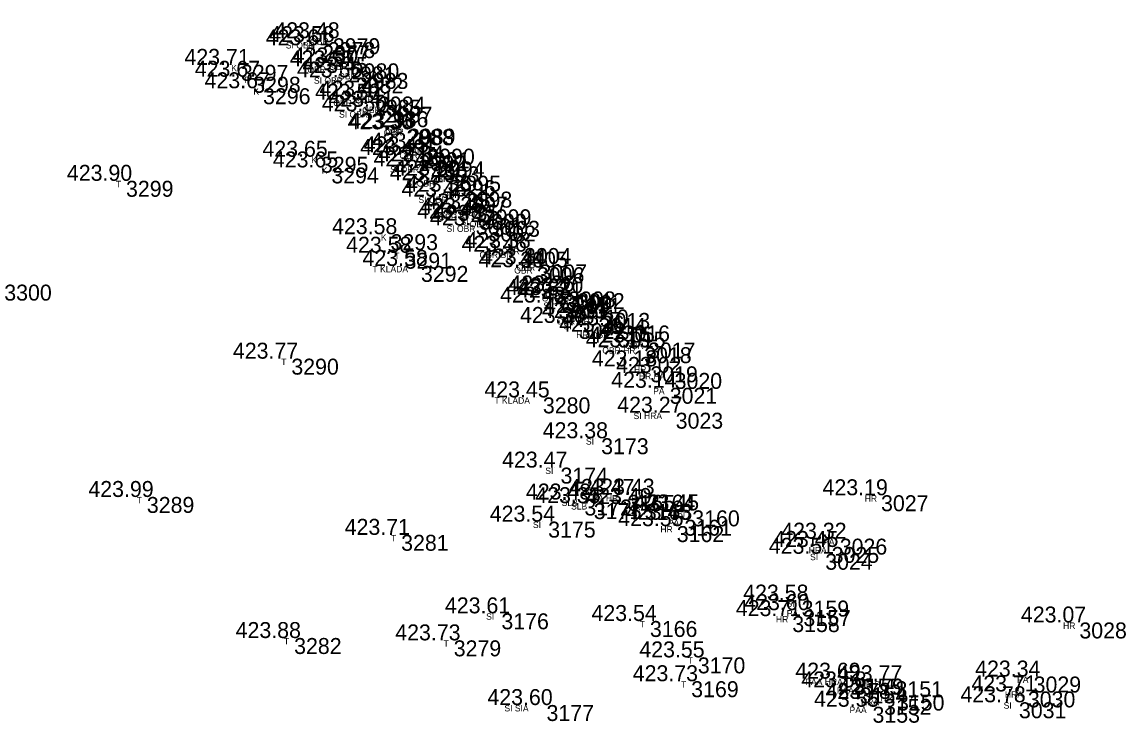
# Model space of a CAD drawing. Extents: x -639390 to -639075, y -1138747 to -1138358.
# Drawn here: x -639236.5 to -639184.6, y -1138516.9 to -1138484 of the extents above; entities that cross this region are included whole.
import ezdxf

# ---------------------------------------------------------------- set-up
doc = ezdxf.new("R2010")
doc.units = 0
for name, color, linetype in [('Vrstva 11', 7, 'Continuous'), ('Vrstva 12', 7, 'Continuous'), ('Vrstva 13', 7, 'Continuous'), ('Vrstva 57', 7, 'Continuous')]:
    doc.layers.add(name, color=color, linetype=linetype)

msp = doc.modelspace()

# ---------------------------------------------------------------- linework, layer by layer
at = {"layer": 'Vrstva 11'}
for p, q in [((-639222.69, -1138485.08), (-639222.69, -1138485.08)), ((-639222.43, -1138484.93), (-639222.43, -1138484.93)), ((-639222.19, -1138484.75), (-639222.19, -1138484.75)), ((-639226.51, -1138486), (-639226.51, -1138486)), ((-639221.47, -1138486.07), (-639221.47, -1138486.07)), ((-639221.3, -1138485.93), (-639221.3, -1138485.93)), ((-639225.93, -1138486.56), (-639225.93, -1138486.56)), ((-639221.11, -1138486.59), (-639221.11, -1138486.59)), ((-639220.87, -1138486.38), (-639220.87, -1138486.38)), ((-639225.47, -1138487.1), (-639225.47, -1138487.1)), ((-639220.25, -1138487.64), (-639220.25, -1138487.64)), ((-639220.07, -1138487.49), (-639220.07, -1138487.49)), ((-639219.93, -1138488.18), (-639219.93, -1138488.18)), ((-639219.74, -1138487.97), (-639219.74, -1138487.97)), ((-639218.73, -1138489.03), (-639218.73, -1138489.03)), ((-639218.66, -1138489), (-639218.66, -1138489)), ((-639222.75, -1138490.32), (-639222.75, -1138490.32)), ((-639218.16, -1138490.24), (-639218.16, -1138490.24)), ((-639217.99, -1138490.11), (-639217.99, -1138490.11)), ((-639217.75, -1138489.94), (-639217.75, -1138489.94)), ((-639222.26, -1138490.82), (-639222.26, -1138490.82)), ((-639217.53, -1138490.77), (-639217.53, -1138490.77)), ((-639217.29, -1138490.54), (-639217.29, -1138490.54)), ((-639216.52, -1138491.21), (-639216.52, -1138491.21)), ((-639231.91, -1138491.45), (-639231.91, -1138491.45)), ((-639216.77, -1138491.42), (-639216.77, -1138491.42)), ((-639216.2, -1138492.19), (-639216.2, -1138492.19)), ((-639215.99, -1138491.96), (-639215.99, -1138491.96)), ((-639215.09, -1138492.79), (-639215.09, -1138492.79)), ((-639215.48, -1138493.23), (-639215.48, -1138493.23)), ((-639215.31, -1138493), (-639215.31, -1138493)), ((-639214.69, -1138493.33), (-639214.69, -1138493.33)), ((-639219.48, -1138493.96), (-639219.48, -1138493.96)), ((-639214.88, -1138493.55), (-639214.88, -1138493.55)), ((-639218.82, -1138494.83), (-639218.82, -1138494.83)), ((-639213.38, -1138494.78), (-639213.38, -1138494.78)), ((-639213.21, -1138494.61), (-639213.21, -1138494.61)), ((-639218.05, -1138495.45), (-639218.05, -1138495.45)), ((-639212.6, -1138495.51), (-639212.6, -1138495.51)), ((-639212.48, -1138495.38), (-639212.48, -1138495.38)), ((-639211.3, -1138496.82), (-639211.3, -1138496.82)), ((-639211.13, -1138496.65), (-639211.13, -1138496.65)), ((-639210.88, -1138496.95), (-639210.88, -1138496.95)), ((-639210.71, -1138496.73), (-639210.71, -1138496.73)), ((-639211.58, -1138497.17), (-639211.58, -1138497.17)), ((-639210.63, -1138498.13), (-639210.63, -1138498.13)), ((-639209.71, -1138497.9), (-639209.71, -1138497.9)), ((-639209.51, -1138497.66), (-639209.51, -1138497.66)), ((-639208.79, -1138498.54), (-639208.79, -1138498.54)), ((-639208.58, -1138498.25), (-639208.58, -1138498.25)), ((-639207.38, -1138499.05), (-639207.38, -1138499.05)), ((-639207.56, -1138499.27), (-639207.56, -1138499.27)), ((-639224.14, -1138499.81), (-639224.14, -1138499.81)), ((-639207.27, -1138500.17), (-639207.27, -1138500.17)), ((-639206.13, -1138500.48), (-639206.13, -1138500.48)), ((-639206.36, -1138501.18), (-639206.36, -1138501.18)), ((-639212.32, -1138501.63), (-639212.32, -1138501.63)), ((-639206.08, -1138502.35), (-639206.08, -1138502.35)), ((-639209.58, -1138503.55), (-639209.58, -1138503.55)), ((-639211.49, -1138504.93), (-639211.49, -1138504.93)), ((-639230.93, -1138506.31), (-639230.93, -1138506.31)), ((-639210.37, -1138506.43), (-639210.37, -1138506.43)), ((-639208.34, -1138506.21), (-639208.34, -1138506.21)), ((-639207.39, -1138506.2), (-639207.39, -1138506.2)), ((-639196.43, -1138506.23), (-639196.43, -1138506.23)), ((-639209.93, -1138506.6), (-639209.93, -1138506.6)), ((-639207.53, -1138506.64), (-639207.53, -1138506.64)), ((-639205.3, -1138506.94), (-639205.3, -1138506.94)), ((-639212.07, -1138507.47), (-639212.07, -1138507.47)), ((-639205.67, -1138507.38), (-639205.67, -1138507.38)), ((-639206.03, -1138507.68), (-639206.03, -1138507.68)), ((-639218.98, -1138508.09), (-639218.98, -1138508.09)), ((-639198.37, -1138508.27), (-639198.37, -1138508.27)), ((-639199.05, -1138508.98), (-639199.05, -1138508.98)), ((-639198.75, -1138508.66), (-639198.75, -1138508.66)), ((-639200.16, -1138511.18), (-639200.16, -1138511.18)), ((-639214.27, -1138511.78), (-639214.27, -1138511.78)), ((-639207.29, -1138512.14), (-639207.29, -1138512.14)), ((-639200.6, -1138511.91), (-639200.6, -1138511.91)), ((-639200.08, -1138511.63), (-639200.08, -1138511.63)), ((-639187.11, -1138512.21), (-639187.11, -1138512.21)), ((-639224.01, -1138512.94), (-639224.01, -1138512.94)), ((-639216.51, -1138513.05), (-639216.51, -1138513.05)), ((-639205.04, -1138513.85), (-639205.04, -1138513.85)), ((-639205.35, -1138514.97), (-639205.35, -1138514.97)), ((-639197.71, -1138514.85), (-639197.71, -1138514.85)), ((-639195.75, -1138514.97), (-639195.75, -1138514.97)), ((-639189.26, -1138514.75), (-639189.26, -1138514.75)), ((-639197.43, -1138515.26), (-639197.43, -1138515.26)), ((-639195.68, -1138515.6), (-639195.68, -1138515.6)), ((-639189.53, -1138515.45), (-639189.53, -1138515.45)), ((-639212.15, -1138516.09), (-639212.15, -1138516.09)), ((-639196.83, -1138516.17), (-639196.83, -1138516.17)), ((-639196.29, -1138515.8), (-639196.29, -1138515.8)), ((-639189.95, -1138515.96), (-639189.95, -1138515.96))]:
    msp.add_line(p, q, dxfattribs=at)

# ---------------------------------------------------------------- texts
at = {"layer": 'Vrstva 12'}
for s, p in [('423.48 ', (-639224.659, -1138484.75)), ('423.61 ', (-639225.065, -1138485.08)), ('423.58 ', (-639224.899, -1138484.93)), ('423.71 ', (-639228.885, -1138486)), ('423.57 ', (-639223.939, -1138486.07)), ('423.50 ', (-639223.799, -1138485.93)), ('423.45 ', (-639223.34, -1138486.38)), ('423.67 ', (-639228.399, -1138486.56)), ('423.56 ', (-639223.596, -1138486.59)), ('423.67 ', (-639227.939, -1138487.1)), ('423.50 ', (-639222.749, -1138487.64)), ('423.42 ', (-639222.539, -1138487.49)), ('423.41 ', (-639222.115, -1138487.97)), ('423.50 ', (-639222.429, -1138488.18)), ('423.36 ', (-639221.216, -1138489.03)), ('423.33 ', (-639221.129, -1138489)), ('423.31 ', (-639220.125, -1138489.94)), ('423.65 ', (-639225.22, -1138490.32)), ('423.49 ', (-639220.629, -1138490.24)), ('423.45 ', (-639220.46, -1138490.11)), ('423.34 ', (-639219.759, -1138490.54)), ('423.65 ', (-639224.73, -1138490.82)), ('423.48 ', (-639219.999, -1138490.77)), ('423.90 ', (-639234.409, -1138491.45)), ('423.43 ', (-639219.239, -1138491.42)), ('423.30 ', (-639219.019, -1138491.21)), ('423.36 ', (-639218.476, -1138491.96)), ('423.46 ', (-639218.686, -1138492.19)), ('423.46 ', (-639217.796, -1138493)), ('423.35 ', (-639217.56, -1138492.79)), ('423.48 ', (-639217.949, -1138493.23)), ('423.47 ', (-639217.349, -1138493.55)), ('423.35 ', (-639217.16, -1138493.33)), ('423.58 ', (-639221.949, -1138493.96)), ('423.38 ', (-639215.679, -1138494.61)), ('423.58 ', (-639221.289, -1138494.83)), ('423.46 ', (-639215.866, -1138494.78)), ('423.58 ', (-639220.519, -1138495.45)), ('423.44 ', (-639215.069, -1138495.51)), ('423.44 ', (-639214.949, -1138495.38)), ('423.32 ', (-639213.769, -1138496.82)), ('423.26 ', (-639213.616, -1138496.65)), ('423.20 ', (-639213.209, -1138496.73)), ('423.43 ', (-639214.049, -1138497.17)), ('423.31 ', (-639213.255, -1138496.95)), ('423.15 ', (-639211.98, -1138497.66)), ('423.36 ', (-639213.116, -1138498.13)), ('423.31 ', (-639212.085, -1138497.9)), ('423.10 ', (-639211.079, -1138498.25)), ('423.26 ', (-639211.276, -1138498.54)), ('423.19 ', (-639210.029, -1138499.27)), ('423.05 ', (-639209.85, -1138499.05)), ('423.77 ', (-639226.609, -1138499.81)), ('423.18 ', (-639209.739, -1138500.17)), ('423.02 ', (-639208.599, -1138500.48)), ('423.14 ', (-639208.829, -1138501.18)), ('423.45 ', (-639214.79, -1138501.63)), ('423.27 ', (-639208.549, -1138502.35)), ('423.38 ', (-639212.049, -1138503.55)), ('423.47 ', (-639213.959, -1138504.93)), ('423.99 ', (-639233.399, -1138506.31)), ('423.48 ', (-639212.839, -1138506.43)), ('423.35 ', (-639212.4, -1138506.6)), ('423.47 ', (-639210.809, -1138506.21)), ('423.49 ', (-639209.999, -1138506.64)), ('423.43 ', (-639209.859, -1138506.2)), ('423.19 ', (-639198.899, -1138506.23)), ('423.45 ', (-639207.77, -1138506.94)), ('423.54 ', (-639214.539, -1138507.47)), ('423.55 ', (-639208.5, -1138507.68)), ('423.45 ', (-639208.14, -1138507.38)), ('423.71 ', (-639221.355, -1138508.09)), ('423.45 ', (-639201.22, -1138508.66)), ('423.32 ', (-639200.839, -1138508.27)), ('423.51 ', (-639201.425, -1138508.98)), ('423.58 ', (-639202.629, -1138511.18)), ('423.61 ', (-639216.645, -1138511.78)), ('423.60 ', (-639202.579, -1138511.63)), ('423.54 ', (-639209.759, -1138512.14)), ('423.71 ', (-639202.975, -1138511.91)), ('423.07 ', (-639189.579, -1138512.21)), ('423.88 ', (-639226.479, -1138512.94)), ('423.73 ', (-639218.979, -1138513.05)), ('423.55 ', (-639207.51, -1138513.85)), ('423.73 ', (-639207.819, -1138514.97)), ('423.69 ', (-639200.179, -1138514.85)), ('423.77 ', (-639198.219, -1138514.97)), ('423.34 ', (-639191.729, -1138514.75)), ('423.58 ', (-639199.899, -1138515.26)), ('423.71 ', (-639191.905, -1138515.45)), ('423.78 ', (-639198.759, -1138515.8)), ('423.79 ', (-639198.149, -1138515.6)), ('423.78 ', (-639192.419, -1138515.96)), ('423.60 ', (-639214.649, -1138516.09)), ('423.55 ', (-639199.3, -1138516.17))]:
    msp.add_text(s, height=0.75, dxfattribs=at).set_placement(p)
at = {"layer": 'Vrstva 13'}
for s, p in [(' 2977', (-639222.69, -1138485.83)), (' 2978', (-639222.43, -1138485.68)), (' 2979', (-639222.19, -1138485.5)), (' 3297', (-639226.51, -1138486.75)), (' 2981', (-639221.47, -1138486.82)), (' 2980', (-639221.3, -1138486.68)), (' 3298', (-639225.93, -1138487.31)), (' 2982', (-639221.11, -1138487.34)), (' 2983', (-639220.87, -1138487.13)), (' 3296', (-639225.47, -1138487.85)), (' 2985', (-639220.25, -1138488.39)), (' 2984', (-639220.07, -1138488.24)), (' 2986', (-639219.93, -1138488.93)), (' 2987', (-639219.74, -1138488.72)), (' 2988', (-639218.73, -1138489.78)), (' 2989', (-639218.66, -1138489.75)), (' 3295', (-639222.75, -1138491.07)), (' 2992', (-639218.16, -1138490.99)), (' 2991', (-639217.99, -1138490.86)), (' 2990', (-639217.75, -1138490.69)), (' 3294', (-639222.26, -1138491.57)), (' 2993', (-639217.53, -1138491.52)), (' 2994', (-639217.29, -1138491.29)), (' 2995', (-639216.52, -1138491.96)), (' 3299', (-639231.91, -1138492.2)), (' 2996', (-639216.77, -1138492.17)), (' 2997', (-639216.2, -1138492.94)), (' 2998', (-639215.99, -1138492.71)), (' 2999', (-639215.09, -1138493.54)), (' 3001', (-639215.48, -1138493.98)), (' 3000', (-639215.31, -1138493.75)), (' 3003', (-639214.69, -1138494.08)), (' 3293', (-639219.48, -1138494.71)), (' 3002', (-639214.88, -1138494.3)), (' 3291', (-639218.82, -1138495.58)), (' 3005', (-639213.38, -1138495.53)), (' 3004', (-639213.21, -1138495.36)), (' 3292', (-639218.05, -1138496.2)), (' 3006', (-639212.6, -1138496.26)), (' 3007', (-639212.48, -1138496.13)), (' 3300', (-639237.63, -1138497.08)), (' 3009', (-639211.3, -1138497.57)), (' 3008', (-639211.13, -1138497.4)), (' 3011', (-639210.88, -1138497.7)), (' 3012', (-639210.71, -1138497.48)), (' 3010', (-639211.58, -1138497.92)), (' 3022', (-639210.63, -1138498.88)), (' 3014', (-639209.71, -1138498.65)), (' 3013', (-639209.51, -1138498.41)), (' 3015', (-639208.79, -1138499.29)), (' 3016', (-639208.58, -1138499)), (' 3017', (-639207.38, -1138499.8)), (' 3018', (-639207.56, -1138500.02)), (' 3290', (-639224.14, -1138500.56)), (' 3019', (-639207.27, -1138500.92)), (' 3020', (-639206.13, -1138501.23)), (' 3021', (-639206.36, -1138501.93)), (' 3280', (-639212.32, -1138502.38)), (' 3023', (-639206.08, -1138503.1)), (' 3173', (-639209.58, -1138504.3)), (' 3174', (-639211.49, -1138505.68)), (' 3289', (-639230.93, -1138507.06)), (' 3172', (-639210.37, -1138507.18)), (' 3165', (-639208.34, -1138506.96)), (' 3164', (-639207.39, -1138506.95)), (' 3027', (-639196.43, -1138506.98)), (' 3171', (-639209.93, -1138507.35)), (' 3163', (-639207.53, -1138507.39)), (' 3160', (-639205.3, -1138507.69)), (' 3175', (-639212.07, -1138508.22)), (' 3161', (-639205.67, -1138508.13)), (' 3162', (-639206.03, -1138508.43)), (' 3281', (-639218.98, -1138508.84)), (' 3026', (-639198.37, -1138509.02)), (' 3024', (-639199.05, -1138509.73)), (' 3025', (-639198.75, -1138509.41)), (' 3159', (-639200.16, -1138511.93)), (' 3157', (-639200.08, -1138512.38)), (' 3176', (-639214.27, -1138512.53)), (' 3166', (-639207.29, -1138512.89)), (' 3158', (-639200.6, -1138512.66)), (' 3028', (-639187.11, -1138512.96)), (' 3282', (-639224.01, -1138513.69)), (' 3279', (-639216.51, -1138513.8)), (' 3170', (-639205.04, -1138514.6)), (' 3169', (-639205.35, -1138515.72)), (' 3155', (-639197.71, -1138515.6)), (' 3154', (-639197.43, -1138516.01)), (' 3151', (-639195.75, -1138515.72)), (' 3029', (-639189.26, -1138515.5)), (' 3150', (-639195.68, -1138516.35)), (' 3030', (-639189.53, -1138516.2)), (' 3177', (-639212.15, -1138516.84)), (' 3153', (-639196.83, -1138516.92)), (' 3152', (-639196.29, -1138516.55)), (' 3031', (-639189.95, -1138516.71))]:
    msp.add_text(s, height=0.75, dxfattribs=at).set_placement(p)
at = {"layer": 'Vrstva 57'}
for s, p in [('SI OBR', (-639224.119, -1138485.23)), ('SI', (-639223.128, -1138485.38)), ('OBR', (-639222.979, -1138485.05)), ('K', (-639226.685, -1138486.3)), ('OBR SI', (-639223.108, -1138486.37)), ('OBR', (-639222.089, -1138486.23)), ('T', (-639226.13, -1138486.86)), ('SI OBR', (-639222.799, -1138486.89)), ('OBR', (-639221.659, -1138486.68)), ('K', (-639225.645, -1138487.4)), ('OBR SI', (-639221.888, -1138487.94)), ('OBR', (-639220.859, -1138487.79)), ('SI OBR', (-639221.619, -1138488.48)), ('OBR', (-639220.529, -1138488.27)), ('OBR', (-639219.519, -1138489.33)), ('OBR', (-639219.449, -1138489.3)), ('K', (-639222.925, -1138490.62)), ('OBR', (-639218.779, -1138490.41)), ('SI', (-639218.598, -1138490.54)), ('OBR', (-639218.539, -1138490.24)), ('K', (-639222.435, -1138491.12)), ('SI OBR', (-639219.219, -1138491.07)), ('OBR', (-639218.079, -1138490.84)), ('OBR', (-639217.309, -1138491.51)), ('T', (-639232.11, -1138491.75)), ('SI OBR', (-639218.459, -1138491.72)), ('SI OBR', (-639217.889, -1138492.49)), ('OBR', (-639216.779, -1138492.26)), ('OBR', (-639215.879, -1138493.09)), ('OBR SI', (-639216.948, -1138493.3)), ('SI', (-639215.918, -1138493.53)), ('OBR', (-639215.479, -1138493.63)), ('K', (-639219.655, -1138494.26)), ('SI OBR', (-639216.569, -1138493.85)), ('T', (-639219.02, -1138495.13)), ('OBR SI', (-639215.018, -1138495.08)), ('OBR', (-639213.999, -1138494.91)), ('T KLADA', (-639220.05, -1138495.75)), ('OBR', (-639213.389, -1138495.81)), ('OBR', (-639213.269, -1138495.68)), ('OBR', (-639212.089, -1138497.12)), ('OBR', (-639211.919, -1138496.95)), ('OBR', (-639211.669, -1138497.25)), ('OBR', (-639211.499, -1138497.03)), ('SI', (-639212.018, -1138497.47)), ('OBR HR', (-639211.399, -1138498.2)), ('SI', (-639211.068, -1138498.43)), ('OBR', (-639210.299, -1138497.96)), ('HR OBR', (-639210.479, -1138498.84)), ('OBR', (-639209.369, -1138498.55)), ('OBR', (-639208.169, -1138499.35)), ('OBR HR', (-639209.249, -1138499.57)), ('T', (-639224.34, -1138500.11)), ('HR', (-639207.759, -1138500.47)), ('HR PA', (-639207.53, -1138500.78)), ('PA', (-639206.86, -1138501.48)), ('T KLADA', (-639214.32, -1138501.93)), ('SI HRA', (-639207.78, -1138502.65)), ('SI', (-639210.018, -1138503.85)), ('SI', (-639211.928, -1138505.23)), ('T', (-639231.13, -1138506.61)), ('SLB', (-639211.159, -1138506.73)), ('PA HR', (-639209.729, -1138506.51)), ('PA', (-639207.89, -1138506.5)), ('HR', (-639196.919, -1138506.53)), ('SLB', (-639210.719, -1138506.9)), ('HR', (-639208.019, -1138506.94)), ('SI', (-639205.738, -1138507.24)), ('SI', (-639212.508, -1138507.77)), ('PA', (-639206.17, -1138507.68)), ('HR', (-639206.519, -1138507.98)), ('T', (-639219.18, -1138508.39)), ('PA', (-639198.87, -1138508.57)), ('HRA', (-639199.55, -1138508.96)), ('SI', (-639199.488, -1138509.28)), ('SI', (-639200.598, -1138511.48)), ('SI', (-639214.708, -1138512.08)), ('T', (-639207.49, -1138512.44)), ('HR', (-639201.089, -1138512.21)), ('PA', (-639200.58, -1138511.93)), ('HR', (-639187.599, -1138512.51)), ('T', (-639224.21, -1138513.24)), ('T', (-639216.71, -1138513.35)), ('T', (-639205.24, -1138514.15)), ('T', (-639205.55, -1138515.27)), ('PAA HRA', (-639199.71, -1138515.15)), ('HR PA', (-639197.15, -1138515.27)), ('PA', (-639189.76, -1138515.05)), ('PAA', (-639198.23, -1138515.56)), ('HR', (-639196.169, -1138515.9)), ('HRA', (-639190.33, -1138515.75)), ('SI SIA', (-639213.85, -1138516.39)), ('PAA', (-639197.63, -1138516.47)), ('HRA', (-639197.09, -1138516.1)), ('SI', (-639190.388, -1138516.26))]:
    msp.add_text(s, height=0.3, dxfattribs=at).set_placement(p)

doc.saveas('drawing.dxf')
